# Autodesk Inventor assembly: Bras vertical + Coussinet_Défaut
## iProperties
Shininess: 64.0
Length Units: 11269
Angle Units: 11279
Time Units: 11290
Mass Units: 11283
Length Display Precision: 3
Angle Display Precision: 2
Compacted: True
Created: 2006-11
Part Number: Bras vertical + Coussinet_Défaut
Document SubType Name: Assembly
Designer: profs_sti
Density: 0.0
Volumn: 0.0
Area: 0.0
PropertySet Name: Model Information
Control State: 0
Master: False
Checked Out: False
Author: profs_sti
